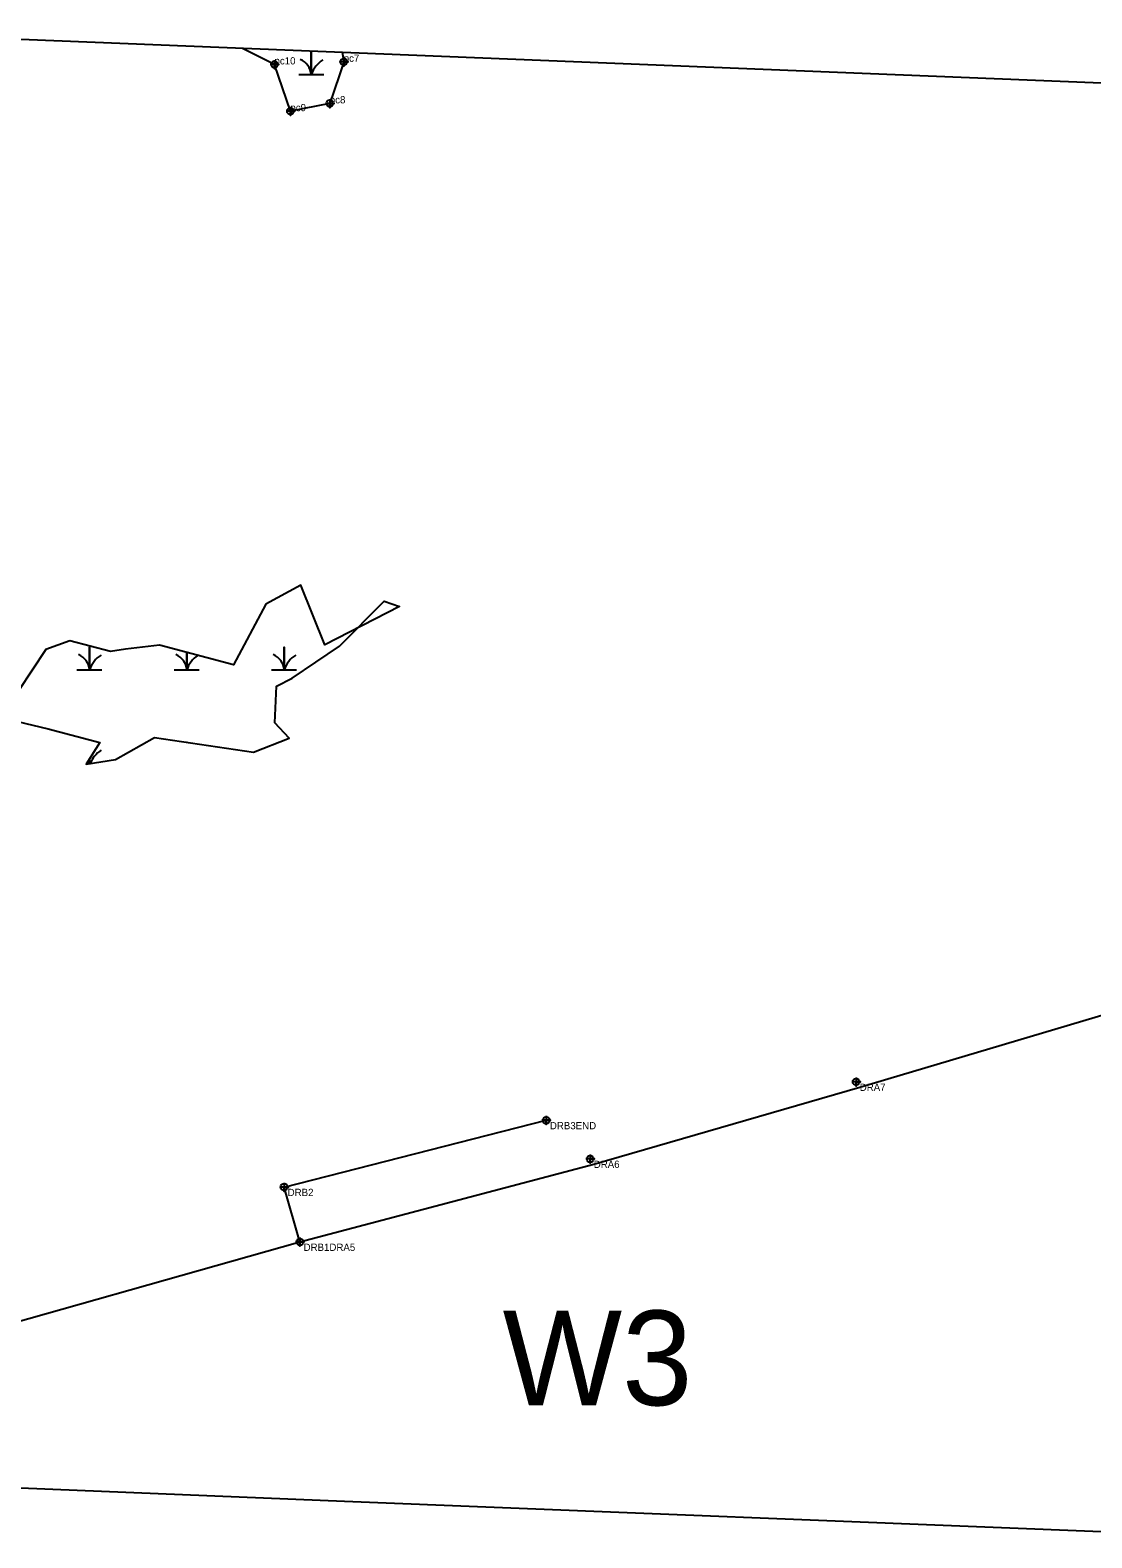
# Model space of a CAD drawing. Extents: x 2071991 to 2268989, y 436479 to 469629.
# Drawn here: x 2231443 to 2232176, y 437865 to 438907 of the extents above; entities that cross this region are included whole.
import ezdxf

# ---------------------------------------------------------------- set-up
doc = ezdxf.new("R2010")
doc.units = 0
for name, color, linetype in [('approx_PSA', 7, 'Continuous'), ('Default', 7, 'Continuous'), ('Exist Environmental Wetland Boundary', 7, 'Continuous'), ('Exist Environmental Wetland Boundary Cogo Comment', 7, 'Continuous'), ('Exist Environmental Wetland Boundary Cogo Point CELL', 7, 'Continuous'), ('Exist Hydro Jurisdictional Stream or Body of Water NEU NonMitigable', 7, 'Continuous'), ('Exist Hydro Jurisdictional Stream or Body of Water NEU NonMitigable Cogo Comment', 7, 'Continuous'), ('Exist Hydro Jurisdictional Stream or Body of Water NEU NonMitigable Cogo Point CELL', 7, 'Continuous'), ('Exist Hydro Swamp or Marsh', 7, 'Continuous')]:
    doc.layers.add(name, color=color, linetype=linetype)

msp = doc.modelspace()

# ---------------------------------------------------------------- linework, layer by layer
at = {"layer": 'approx_PSA'}
for p, q in [((2231278.7, 438906.7), (2233358.1, 438822.7)), ((2231659.6, 437890.5), (2231238.3, 437907.5)), ((2232283.6, 437865.3), (2231659.6, 437890.5))]:
    msp.add_line(p, q, dxfattribs=at)
at = {"layer": 'Exist Environmental Wetland Boundary'}
for points in [[(2231658, 438891.4), (2231659.1, 438884.8), (2231649.5, 438856.1), (2231622.3, 438850.7), (2231611.3, 438883), (2231589.1, 438894.1)], [(2231401.9, 438436.7), (2231455, 438424), (2231490.6, 438414.7), (2231481.3, 438399.8), (2231501.6, 438402.8), (2231528.4, 438418), (2231596.7, 438407.9), (2231621.4, 438417.7), (2231611.6, 438428.2), (2231612.8, 438453.6), (2231623.5, 438459.2), (2231656.1, 438481.3), (2231687.1, 438512.2), (2231697.6, 438508.7), (2231646.1, 438482.2), (2231629.6, 438523.4), (2231605.4, 438510.3), (2231582.9, 438468.2), (2231531.8, 438481.9), (2231508.5, 438479.1), (2231498.1, 438477.4), (2231469.9, 438484.9), (2231453.4, 438479), (2231434.6, 438450.4)]]:
    msp.add_lwpolyline(points, dxfattribs=at)
at = {"layer": 'Exist Environmental Wetland Boundary Cogo Point CELL'}
for points in [[(2231611.3, 438886), (2231611.3, 438880), (2231611.3, 438883), (2231614.3, 438883), (2231608.3, 438883)], [(2231659.1, 438887.8), (2231659.1, 438881.8), (2231659.1, 438884.8), (2231662.1, 438884.8), (2231656.1, 438884.8)], [(2231649.5, 438859.1), (2231649.5, 438853.1), (2231649.5, 438856.1), (2231652.5, 438856.1), (2231646.5, 438856.1)], [(2231622.3, 438853.7), (2231622.3, 438847.7), (2231622.3, 438850.7), (2231625.3, 438850.7), (2231619.3, 438850.7)]]:
    msp.add_lwpolyline(points, dxfattribs=at)
for centre in [(2231611.3, 438883), (2231659.1, 438884.8), (2231649.5, 438856.1), (2231622.3, 438850.7)]:
    msp.add_circle(centre, 2.34, dxfattribs=at)
at = {"layer": 'Exist Hydro Jurisdictional Stream or Body of Water NEU NonMitigable'}
for points in [[(2231056.2, 437914.4), (2231371.5, 437996.9), (2231628.9, 438069.7), (2231831.8, 438123.3), (2232015.5, 438176.5), (2232340.7, 438273.3), (2232446.5, 438459.8), (2232614.8, 438672.9), (2232699.7, 438654.7)], [(2231628.9, 438069.7), (2231617.9, 438107.6), (2231799, 438153.7)]]:
    msp.add_lwpolyline(points, dxfattribs=at)
at = {"layer": 'Exist Hydro Jurisdictional Stream or Body of Water NEU NonMitigable Cogo Point CELL'}
for points in [[(2232013, 438183.3), (2232013, 438177.3), (2232013, 438180.3), (2232016, 438180.3), (2232010, 438180.3)], [(2231799, 438156.7), (2231799, 438150.7), (2231799, 438153.7), (2231802, 438153.7), (2231796, 438153.7)], [(2231829.3, 438130), (2231829.3, 438124), (2231829.3, 438127), (2231832.3, 438127), (2231826.3, 438127)], [(2231617.9, 438110.6), (2231617.9, 438104.6), (2231617.9, 438107.6), (2231620.9, 438107.6), (2231614.9, 438107.6)], [(2231628.9, 438072.7), (2231628.9, 438066.7), (2231628.9, 438069.7), (2231631.9, 438069.7), (2231625.9, 438069.7)]]:
    msp.add_lwpolyline(points, dxfattribs=at)
for centre in [(2232013, 438180.3), (2231799, 438153.7), (2231829.3, 438127), (2231617.9, 438107.6), (2231628.9, 438069.7)]:
    msp.add_circle(centre, 2.34, dxfattribs=at)
at = {"layer": 'Exist Hydro Swamp or Marsh'}
for p, q in [((2231483.5, 438400.1), (2231483.5, 438403.4)), ((2231483.5, 438403.4), (2231483.5, 438400.1))]:
    msp.add_line(p, q, dxfattribs=at)
for points in [[(2231628.1, 438876), (2231636.7, 438876), (2231636.7, 438891.8), (2231636.7, 438876), (2231645.3, 438876)], [(2231474.9, 438464.9), (2231483.5, 438464.9), (2231483.5, 438480.6), (2231483.5, 438464.9), (2231492.1, 438464.9)], [(2231542.1, 438464.9), (2231550.7, 438464.9), (2231550.7, 438476.8)], [(2231550.7, 438476.8), (2231550.7, 438464.9), (2231559.3, 438464.9)], [(2231609.3, 438464.9), (2231617.9, 438464.9), (2231617.9, 438480.6), (2231617.9, 438464.9), (2231626.5, 438464.9)], [(2231550.7, 438414.7), (2231550.7, 438414.9), (2231550.7, 438414.7)]]:
    msp.add_lwpolyline(points, dxfattribs=at)
for centre, radius, start, end in [((2231624.4, 438875.1), 12.3, 4.1403, 67.535), ((2231655, 438869.9), 19.2, 122.1274, 161.6222), ((2231471.3, 438464), 12.3, 4.1403, 67.535), ((2231501.8, 438458.8), 19.2, 122.1274, 161.6222), ((2231538.5, 438464), 12.3, 4.1403, 67.535), ((2231569, 438458.8), 19.2, 123.7185, 161.6222), ((2231605.7, 438464), 12.3, 4.1403, 67.535), ((2231636.2, 438458.8), 19.2, 122.1274, 161.6222), ((2231471.3, 438398.2), 12.3, 8.9627, 19.4368), ((2231501.8, 438393), 19.2, 122.1274, 158.1093)]:
    msp.add_arc(centre, radius, start, end, dxfattribs=at)

# ---------------------------------------------------------------- texts
at = {"layer": 'Default'}
msp.add_text('W3', height=65.34, dxfattribs=at).set_placement((2231768.9, 437956.9))
at = {"layer": 'Exist Environmental Wetland Boundary Cogo Comment'}
for s, p in [('pc7', (2231659.1, 438884.8)), ('pc10', (2231611.3, 438883)), ('pc8', (2231649.5, 438856.1)), ('pc9', (2231622.3, 438850.7))]:
    msp.add_text(s, height=5, dxfattribs=at).set_placement(p)
at = {"layer": 'Exist Hydro Jurisdictional Stream or Body of Water NEU NonMitigable Cogo Comment'}
for s, p in [('DRA7', (2232015.5, 438174)), ('DRB3END', (2231801.5, 438147.5)), ('DRA6', (2231831.8, 438120.8)), ('DRB2', (2231620.4, 438101.4)), ('DRB1DRA5', (2231631.4, 438063.5))]:
    msp.add_text(s, height=5, dxfattribs=at).set_placement(p)

doc.saveas('drawing.dxf')
